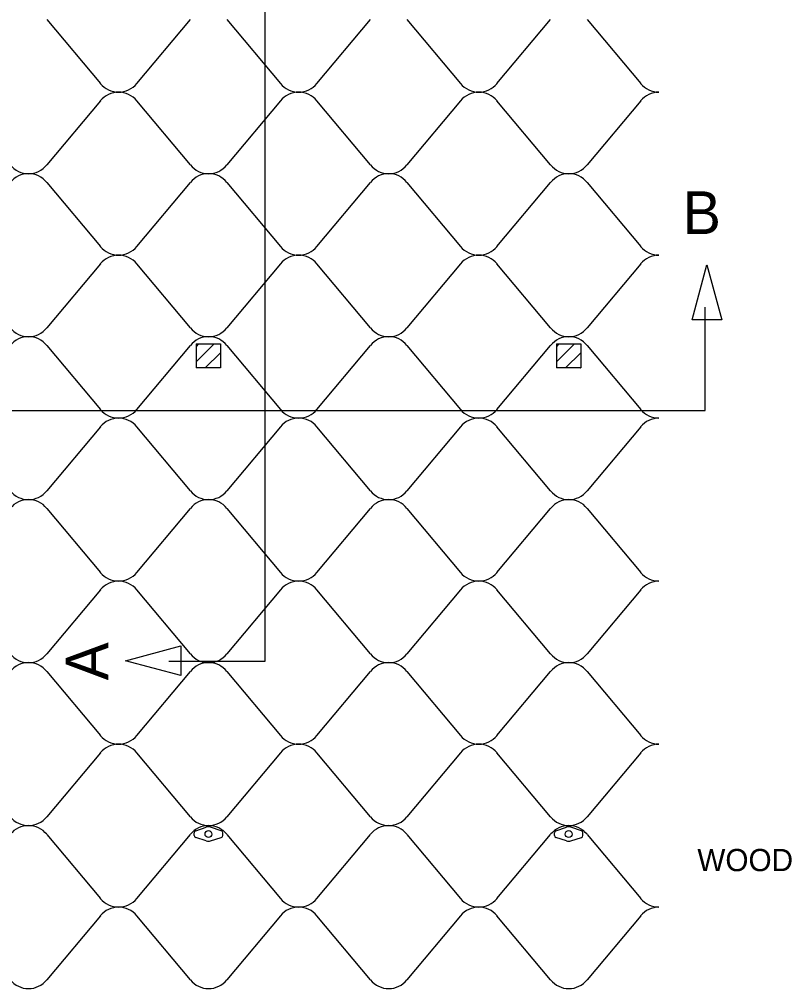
# Model space of a CAD drawing. Extents: x 638850 to 644908, y 297188 to 298900.
# Drawn here: x 641514.3 to 641612.1, y 297623 to 297746.5 of the extents above; entities that cross this region are included whole.
import ezdxf

# ---------------------------------------------------------------- set-up
doc = ezdxf.new("R2010")
doc.units = 0
for name, color, linetype in [('3', 7, 'Continuous'), ('4', 7, 'Continuous'), ('5', 7, 'Continuous'), ('6', 7, 'Continuous')]:
    doc.layers.add(name, color=color, linetype=linetype)

msp = doc.modelspace()

# ---------------------------------------------------------------- linework, layer by layer
at = {"layer": '4'}
for p, q in [((641517.8, 297746.55), (641524.64, 297738.38)), ((641529.29, 297738.38), (641536.12, 297746.55)), ((641540.77, 297746.55), (641547.6, 297738.38)), ((641552.25, 297738.38), (641559.08, 297746.55)), ((641563.73, 297746.55), (641570.56, 297738.38)), ((641575.21, 297738.38), (641582.05, 297746.55)), ((641586.69, 297746.55), (641593.53, 297738.38)), ((641524.64, 297736.16), (641517.8, 297727.99)), ((641536.12, 297727.99), (641529.29, 297736.16)), ((641547.6, 297736.16), (641540.77, 297727.99)), ((641559.08, 297727.99), (641552.25, 297736.16)), ((641570.56, 297736.16), (641563.73, 297727.99)), ((641582.05, 297727.99), (641575.21, 297736.16)), ((641593.53, 297736.16), (641586.69, 297727.99)), ((641517.8, 297725.77), (641524.64, 297717.6)), ((641529.29, 297717.6), (641536.12, 297725.77)), ((641540.77, 297725.77), (641547.6, 297717.6)), ((641552.25, 297717.6), (641559.08, 297725.77)), ((641563.73, 297725.77), (641570.56, 297717.6)), ((641575.21, 297717.6), (641582.05, 297725.77)), ((641586.69, 297725.77), (641593.53, 297717.6)), ((641524.64, 297715.38), (641517.8, 297707.22)), ((641536.12, 297707.22), (641529.29, 297715.38)), ((641547.6, 297715.38), (641540.77, 297707.22)), ((641559.08, 297707.22), (641552.25, 297715.38)), ((641570.56, 297715.38), (641563.73, 297707.22)), ((641582.05, 297707.22), (641575.21, 297715.38)), ((641593.53, 297715.38), (641586.69, 297707.22)), ((641517.8, 297704.99), (641524.64, 297696.83)), ((641529.29, 297696.83), (641536.12, 297704.99)), ((641540.77, 297704.99), (641547.6, 297696.83)), ((641552.25, 297696.83), (641559.08, 297704.99)), ((641563.73, 297704.99), (641570.56, 297696.83)), ((641575.21, 297696.83), (641582.05, 297704.99)), ((641586.69, 297704.99), (641593.53, 297696.83)), ((641524.64, 297694.61), (641517.8, 297686.44)), ((641536.12, 297686.44), (641529.29, 297694.61)), ((641547.6, 297694.61), (641540.77, 297686.44)), ((641559.08, 297686.44), (641552.25, 297694.61)), ((641570.56, 297694.61), (641563.73, 297686.44)), ((641582.05, 297686.44), (641575.21, 297694.61)), ((641593.53, 297694.61), (641586.69, 297686.44)), ((641517.8, 297684.22), (641524.64, 297676.05)), ((641529.29, 297676.05), (641536.12, 297684.22)), ((641540.77, 297684.22), (641547.6, 297676.05)), ((641552.25, 297676.05), (641559.08, 297684.22)), ((641563.73, 297684.22), (641570.56, 297676.05)), ((641575.21, 297676.05), (641582.05, 297684.22)), ((641586.69, 297684.22), (641593.53, 297676.05)), ((641524.64, 297673.83), (641517.8, 297665.66)), ((641536.12, 297665.66), (641529.29, 297673.83)), ((641547.6, 297673.83), (641540.77, 297665.66)), ((641559.08, 297665.66), (641552.25, 297673.83)), ((641570.56, 297673.83), (641563.73, 297665.66)), ((641582.05, 297665.66), (641575.21, 297673.83)), ((641593.53, 297673.83), (641586.69, 297665.66)), ((641517.8, 297663.44), (641524.64, 297655.27)), ((641529.29, 297655.27), (641536.12, 297663.44)), ((641540.77, 297663.44), (641547.6, 297655.27)), ((641552.25, 297655.27), (641559.08, 297663.44)), ((641563.73, 297663.44), (641570.56, 297655.27)), ((641575.21, 297655.27), (641582.05, 297663.44)), ((641586.69, 297663.44), (641593.53, 297655.27)), ((641524.64, 297653.05), (641517.8, 297644.89)), ((641536.12, 297644.89), (641529.29, 297653.05)), ((641547.6, 297653.05), (641540.77, 297644.89)), ((641559.08, 297644.89), (641552.25, 297653.05)), ((641570.56, 297653.05), (641563.73, 297644.89)), ((641582.05, 297644.89), (641575.21, 297653.05)), ((641593.53, 297653.05), (641586.69, 297644.89)), ((641517.8, 297642.66), (641524.64, 297634.5)), ((641529.29, 297634.5), (641536.12, 297642.66)), ((641540.77, 297642.66), (641547.6, 297634.5)), ((641552.25, 297634.5), (641559.08, 297642.66)), ((641563.73, 297642.66), (641570.56, 297634.5)), ((641575.21, 297634.5), (641582.05, 297642.66)), ((641586.69, 297642.66), (641593.53, 297634.5)), ((641524.64, 297632.28), (641517.8, 297624.11)), ((641536.12, 297624.11), (641529.29, 297632.28)), ((641547.6, 297632.28), (641540.77, 297624.11)), ((641559.08, 297624.11), (641552.25, 297632.28)), ((641570.56, 297632.28), (641563.73, 297624.11)), ((641582.05, 297624.11), (641575.21, 297632.28)), ((641593.53, 297632.28), (641586.69, 297624.11))]:
    msp.add_line(p, q, dxfattribs=at)
for centre, start, end in [((641526.96, 297740.26), 218.9482, 270), ((641526.96, 297740.26), 270, 321.0518), ((641549.92, 297740.26), 218.9482, 270), ((641549.92, 297740.26), 270, 321.0518), ((641572.89, 297740.26), 218.9482, 270), ((641572.89, 297740.26), 270, 321.0518), ((641595.85, 297740.26), 218.9482, 270), ((641526.96, 297734.28), 90, 141.0518), ((641526.96, 297734.28), 38.9482, 90), ((641549.92, 297734.28), 90, 141.0518), ((641549.92, 297734.28), 38.9482, 90), ((641572.89, 297734.28), 90, 141.0518), ((641572.89, 297734.28), 38.9482, 90), ((641595.85, 297734.28), 90, 141.0518), ((641515.48, 297729.87), 218.9482, 270), ((641515.48, 297729.87), 270, 321.0518), ((641538.44, 297729.87), 218.9482, 270), ((641538.44, 297729.87), 270, 321.0518), ((641561.41, 297729.87), 218.9482, 270), ((641561.41, 297729.87), 270, 321.0518), ((641584.37, 297729.87), 218.9482, 270), ((641584.37, 297729.87), 270, 321.0518), ((641515.48, 297723.89), 90, 141.0518), ((641515.48, 297723.89), 38.9482, 90), ((641538.44, 297723.89), 90, 141.0518), ((641538.44, 297723.89), 38.9482, 90), ((641561.41, 297723.89), 90, 141.0518), ((641561.41, 297723.89), 38.9482, 90), ((641584.37, 297723.89), 90, 141.0518), ((641584.37, 297723.89), 38.9482, 90), ((641526.96, 297719.48), 218.9482, 270), ((641526.96, 297719.48), 270, 321.0518), ((641549.92, 297719.48), 218.9482, 270), ((641549.92, 297719.48), 270, 321.0518), ((641572.89, 297719.48), 218.9482, 270), ((641572.89, 297719.48), 270, 321.0518), ((641595.85, 297719.48), 218.9482, 270), ((641526.96, 297713.5), 90, 141.0518), ((641526.96, 297713.5), 38.9482, 90), ((641549.92, 297713.5), 90, 141.0518), ((641549.92, 297713.5), 38.9482, 90), ((641572.89, 297713.5), 90, 141.0518), ((641572.89, 297713.5), 38.9482, 90), ((641595.85, 297713.5), 90, 141.0518), ((641515.48, 297709.09), 218.9482, 270), ((641515.48, 297709.09), 270, 321.0518), ((641538.44, 297709.09), 218.9482, 270), ((641538.44, 297709.09), 270, 321.0518), ((641561.41, 297709.09), 218.9482, 270), ((641561.41, 297709.09), 270, 321.0518), ((641584.37, 297709.09), 218.9482, 270), ((641584.37, 297709.09), 270, 321.0518), ((641515.48, 297703.11), 90, 141.0518), ((641515.48, 297703.11), 38.9482, 90), ((641538.44, 297703.11), 90, 141.0518), ((641538.44, 297703.11), 38.9482, 90), ((641561.41, 297703.11), 90, 141.0518), ((641561.41, 297703.11), 38.9482, 90), ((641584.37, 297703.11), 90, 141.0518), ((641584.37, 297703.11), 38.9482, 90), ((641526.96, 297698.71), 218.9482, 270), ((641526.96, 297698.71), 270, 321.0518), ((641549.92, 297698.71), 218.9482, 270), ((641549.92, 297698.71), 270, 321.0518), ((641572.89, 297698.71), 218.9482, 270), ((641572.89, 297698.71), 270, 321.0518), ((641595.85, 297698.71), 218.9482, 270), ((641526.96, 297692.73), 90, 141.0518), ((641526.96, 297692.73), 38.9482, 90), ((641549.92, 297692.73), 90, 141.0518), ((641549.92, 297692.73), 38.9482, 90), ((641572.89, 297692.73), 90, 141.0518), ((641572.89, 297692.73), 38.9482, 90), ((641595.85, 297692.73), 90, 141.0518), ((641515.48, 297688.32), 218.9482, 270), ((641515.48, 297688.32), 270, 321.0518), ((641538.44, 297688.32), 218.9482, 270), ((641538.44, 297688.32), 270, 321.0518), ((641561.41, 297688.32), 218.9482, 270), ((641561.41, 297688.32), 270, 321.0518), ((641584.37, 297688.32), 218.9482, 270), ((641584.37, 297688.32), 270, 321.0518), ((641515.48, 297682.34), 90, 141.0518), ((641515.48, 297682.34), 38.9482, 90), ((641538.44, 297682.34), 90, 141.0518), ((641538.44, 297682.34), 38.9482, 90), ((641561.41, 297682.34), 90, 141.0518), ((641561.41, 297682.34), 38.9482, 90), ((641584.37, 297682.34), 90, 141.0518), ((641584.37, 297682.34), 38.9482, 90), ((641526.96, 297677.93), 218.9482, 270), ((641526.96, 297677.93), 270, 321.0518), ((641549.92, 297677.93), 218.9482, 270), ((641549.92, 297677.93), 270, 321.0518), ((641572.89, 297677.93), 218.9482, 270), ((641572.89, 297677.93), 270, 321.0518), ((641595.85, 297677.93), 218.9482, 270), ((641526.96, 297671.95), 90, 141.0518), ((641526.96, 297671.95), 38.9482, 90), ((641549.92, 297671.95), 90, 141.0518), ((641549.92, 297671.95), 38.9482, 90), ((641572.89, 297671.95), 90, 141.0518), ((641572.89, 297671.95), 38.9482, 90), ((641595.85, 297671.95), 90, 141.0518), ((641515.48, 297667.54), 218.9482, 270), ((641515.48, 297667.54), 270, 321.0518), ((641538.44, 297667.54), 218.9482, 270), ((641538.44, 297667.54), 270, 321.0518), ((641561.41, 297667.54), 218.9482, 270), ((641561.41, 297667.54), 270, 321.0518), ((641584.37, 297667.54), 218.9482, 270), ((641584.37, 297667.54), 270, 321.0518), ((641515.48, 297661.56), 90, 141.0518), ((641515.48, 297661.56), 38.9482, 90), ((641538.44, 297661.56), 90, 141.0518), ((641538.44, 297661.56), 38.9482, 90), ((641561.41, 297661.56), 90, 141.0518), ((641561.41, 297661.56), 38.9482, 90), ((641584.37, 297661.56), 90, 141.0518), ((641584.37, 297661.56), 38.9482, 90), ((641526.96, 297657.15), 218.9482, 270), ((641526.96, 297657.15), 270, 321.0518), ((641549.92, 297657.15), 218.9482, 270), ((641549.92, 297657.15), 270, 321.0518), ((641572.89, 297657.15), 218.9482, 270), ((641572.89, 297657.15), 270, 321.0518), ((641595.85, 297657.15), 218.9482, 270), ((641526.96, 297651.17), 90, 141.0518), ((641526.96, 297651.17), 38.9482, 90), ((641549.92, 297651.17), 90, 141.0518), ((641549.92, 297651.17), 38.9482, 90), ((641572.89, 297651.17), 90, 141.0518), ((641572.89, 297651.17), 38.9482, 90), ((641595.85, 297651.17), 90, 141.0518), ((641515.48, 297646.77), 218.9482, 270), ((641515.48, 297646.77), 270, 321.0518), ((641538.44, 297646.77), 218.9482, 270), ((641538.44, 297646.77), 270, 321.0518), ((641561.41, 297646.77), 218.9482, 270), ((641561.41, 297646.77), 270, 321.0518), ((641584.37, 297646.77), 218.9482, 270), ((641584.37, 297646.77), 270, 321.0518), ((641515.48, 297640.79), 90, 141.0518), ((641515.48, 297640.79), 38.9482, 90), ((641538.44, 297640.79), 90, 141.0518), ((641538.44, 297640.79), 38.9482, 90), ((641561.41, 297640.79), 90, 141.0518), ((641561.41, 297640.79), 38.9482, 90), ((641584.37, 297640.79), 90, 141.0518), ((641584.37, 297640.79), 38.9482, 90), ((641526.96, 297636.38), 218.9482, 270), ((641526.96, 297636.38), 270, 321.0518), ((641549.92, 297636.38), 218.9482, 270), ((641549.92, 297636.38), 270, 321.0518), ((641572.89, 297636.38), 218.9482, 270), ((641572.89, 297636.38), 270, 321.0518), ((641595.85, 297636.38), 218.9482, 270), ((641526.96, 297630.4), 90, 141.0518), ((641526.96, 297630.4), 38.9482, 90), ((641549.92, 297630.4), 90, 141.0518), ((641549.92, 297630.4), 38.9482, 90), ((641572.89, 297630.4), 90, 141.0518), ((641572.89, 297630.4), 38.9482, 90), ((641595.85, 297630.4), 90, 141.0518), ((641515.48, 297625.99), 218.9482, 270), ((641515.48, 297625.99), 270, 321.0518), ((641538.44, 297625.99), 218.9482, 270), ((641538.44, 297625.99), 270, 321.0518), ((641561.41, 297625.99), 218.9482, 270), ((641561.41, 297625.99), 270, 321.0518), ((641584.37, 297625.99), 218.9482, 270), ((641584.37, 297625.99), 270, 321.0518)]:
    msp.add_arc(centre, 2.99, start, end, dxfattribs=at)
at = {"layer": '5'}
for p, q in [((641545.62, 297810.51), (641545.62, 297664.71)), ((641601.73, 297696.7), (641601.73, 297709.88)), ((641405.39, 297696.7), (641601.73, 297696.7)), ((641545.62, 297664.71), (641533.36, 297664.71))]:
    msp.add_line(p, q, dxfattribs=at)
for points in [[(641600.08, 297708.24), (641601.97, 297715.26), (641603.86, 297708.24)], [(641534.88, 297662.92), (641527.86, 297664.8), (641534.88, 297666.69)]]:
    msp.add_lwpolyline(points, close=True, dxfattribs=at)
at = {"layer": '6'}
for p, q in [((641536.86, 297705.17), (641539.96, 297705.17)), ((641536.86, 297705.17), (641536.86, 297702.11)), ((641536.86, 297702.89), (641539.14, 297705.17)), ((641536.86, 297704.82), (641537.21, 297705.17)), ((641539.96, 297705.17), (641539.96, 297702.11)), ((641582.79, 297705.17), (641585.89, 297705.17)), ((641582.79, 297705.17), (641582.79, 297702.11)), ((641582.79, 297702.89), (641585.07, 297705.17)), ((641582.79, 297704.82), (641583.14, 297705.17)), ((641585.89, 297705.17), (641585.89, 297702.11)), ((641538.01, 297702.11), (641539.96, 297704.05)), ((641583.94, 297702.11), (641585.89, 297704.05)), ((641539.96, 297702.11), (641536.86, 297702.11)), ((641539.95, 297702.11), (641539.96, 297702.12)), ((641585.89, 297702.11), (641582.79, 297702.11)), ((641585.87, 297702.11), (641585.89, 297702.12)), ((641536.6, 297642.53), (641536.6, 297642.87)), ((641536.8, 297643.13), (641538.15, 297643.57)), ((641540.05, 297643.13), (641538.7, 297643.57)), ((641540.25, 297642.53), (641540.25, 297642.87)), ((641582.53, 297642.53), (641582.53, 297642.87)), ((641582.72, 297643.13), (641584.07, 297643.57)), ((641585.98, 297643.13), (641584.63, 297643.57)), ((641586.17, 297642.53), (641586.17, 297642.87)), ((641538.15, 297641.83), (641536.8, 297642.26)), ((641538.7, 297641.83), (641540.05, 297642.26)), ((641584.07, 297641.83), (641582.72, 297642.26)), ((641584.63, 297641.83), (641585.98, 297642.26))]:
    msp.add_line(p, q, dxfattribs=at)
for centre in [(641538.42, 297642.7), (641584.35, 297642.7)]:
    msp.add_circle(centre, 0.433, dxfattribs=at)
for centre, radius, start, end in [((641536.88, 297642.87), 0.279, 107.7019, 180), ((641538.42, 297642.7), 0.911, 72.2974, 107.7022), ((641539.97, 297642.87), 0.279, 359.9999, 72.298), ((641582.81, 297642.87), 0.279, 107.7019, 180), ((641584.35, 297642.7), 0.911, 72.2974, 107.7022), ((641585.89, 297642.87), 0.279, 359.9999, 72.298), ((641536.88, 297642.53), 0.279, 180, 252.2979), ((641538.42, 297642.7), 0.911, 252.2975, 287.7021), ((641539.97, 297642.53), 0.279, 287.702, 360), ((641582.81, 297642.53), 0.279, 180, 252.2979), ((641584.35, 297642.7), 0.911, 252.2975, 287.7021), ((641585.89, 297642.53), 0.279, 287.702, 360)]:
    msp.add_arc(centre, radius, start, end, dxfattribs=at)

# ---------------------------------------------------------------- texts
at = {"layer": '3'}
msp.add_text('WOOD STAKES (AS INDICATED - SPACING VARIES)', height=2.8341, dxfattribs=at).set_placement((641600.75, 297637.97))
at = {"layer": '5'}
msp.add_text('B', height=5.45, dxfattribs=at).set_placement((641598.9, 297719.18))
msp.add_text('A', height=5.45, rotation=90, dxfattribs=at).set_placement((641525.67, 297662.29))

doc.saveas('drawing.dxf')
